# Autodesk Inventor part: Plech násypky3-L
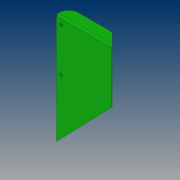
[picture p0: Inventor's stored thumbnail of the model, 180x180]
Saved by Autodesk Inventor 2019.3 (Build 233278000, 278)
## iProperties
Created: 2019-02
Part Number: Plech násypky3-L
Material: Ocel, měkká, svařovaná
Document SubType Name: Plech
Designer: B-hon
Density: 7.85 g/cm^3
Sheet Metal Rule: Výchozí_mm
Appearance: Tmavě zelená
Author: B-hon
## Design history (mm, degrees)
node "Plocha1"
  sketch "Náčrt1"
    geometry: L1 (114, 118.05)-(114, 229.75); L2 (114, 229.75)-(0, 229.75); L3 (0, 229.75)-(0, 0); L4 (114, 118.05)-(0, 0)
    constraints: 8 end point, 1 parallel, 1 perpendicular, 1 vertical
    dimensions: "d0" = 114 distance of L2.end L1.end; "d2" = 111.7 distance of L1.start L1.end; "d3" = 136 deg angle of L4 L1
fillet "Zaoblení1" dims "d5" = 2
node "Obruba1"
fillet "Zaoblení2" dims "d22" = 20
sketch "Náčrt5"
  geometry: L1 (117.517, -5.517)-(89.185, 22.815); L2 (89.185, 22.815)-(117.079, 27.671); L3 (117.079, 27.671)-(117.517, -5.517); 2 further points
  constraints: 6 end point, 1 point on line
extrude "Vysunutí2" cut sketch "Náčrt5" distance "d25" = 10; taper "d26" = 0 deg
sketch "Náčrt6"
  geometry: L1 (0, 0)-(0, 225.75) reference; L2 (0, 229.75)-(-112, 229.75) reference; 1 further point
  dimensions: "d27" = 10 distance from line of L1 point (-10, 214.75); "d28" = 15 distance from line of L2 point (-10, 214.75)
hole "Díra1" sketch "Náčrt6" at (-10, 214.75) diameter "d29" = 6.5; stored, may be unused: countersink angle "d33" = 90 deg, drill point angle "d35" = 118 deg; dims "d30" = 6, "d31" = 4, "d32" = 2, "d34" = 2 (= Tloušťka)
pattern_linear "Obdélníkové pole1" dims "d38" = 90
node "Těleso1"
feature "Deska1" dims "d4" = 2 (= Tloušťka)
sketch "Náčrt2"
  geometry: L1 through (-57, 0) direction (1, 0); L2 through (0, 12.5) direction (0, 1); L3 (0, 25)-(-114, 25); L4 (-114, 25)-(-114, 0)
  constraints: 6 end point, 1 horizontal, 1 perpendicular, 1 vertical
feature "Deska2" dims "d4" = 2 (= Tloušťka), "d6" = 2 (= ŠířkaVýštipu), "d7" = 1 (= HloubkaVýštipu), "d8" = 4 (= MinimálníZbytek), "d9" = 2 (= PřechodovýPoloměr), "d10" = 25, "d11" = -90 deg, "d12" = 2 (= PoloměrOhybu), "d13" = 8 (= VelikostRohovéhoVýštipu), "d14" = 2 (= VelikostMezery), "d15" = 2 (= VelikostJacobihoPoloměru), "MezeraVystřižení" = 0.01
feature "Ohyb1" dims "d4" = 2 (= Tloušťka), "d6" = 2 (= ŠířkaVýštipu), "d7" = 1 (= HloubkaVýštipu), "d8" = 4 (= MinimálníZbytek), "d9" = 2 (= PřechodovýPoloměr), "d10" = 25, "d11" = -90 deg, "d12" = 2 (= PoloměrOhybu), "MezeraVystřižení" = 0.01
feature "Roh1" dims "d10" = 25, "d11" = -90 deg, "d13" = 8 (= VelikostRohovéhoVýštipu), "d14" = 2 (= VelikostMezery), "d15" = 2 (= VelikostJacobihoPoloměru)
other parameters: "Tloušťka" = 2 (derived), "KSoučinitel" = 4.4, "PoloměrOhybu" = 2 (= Tloušťka), "ŠířkaVýštipu" = 2 (= Tloušťka), "HloubkaVýštipu" = 1 (= 0.5 x Tloušťka), "VelikostRohovéhoVýštipu" = 8 (= 4 x Tloušťka), "MinimálníZbytek" = 4 (= 2 x Tloušťka), "PřechodovýPoloměr" = 2 (= PoloměrOhybu), "VelikostJacobihoPoloměru" = 2 (= PoloměrOhybu), "VelikostMezery" = 2 (= Tloušťka)
